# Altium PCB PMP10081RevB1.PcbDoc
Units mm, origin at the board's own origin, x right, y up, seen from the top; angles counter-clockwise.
Board outline 49.53 x 78.74 mm, 4 copper layers (Top Layer, inner 1, inner 2, Bottom Layer), stack 2.028 mm thick; 62 components, 28 nets, 143 pads, 49 vias.
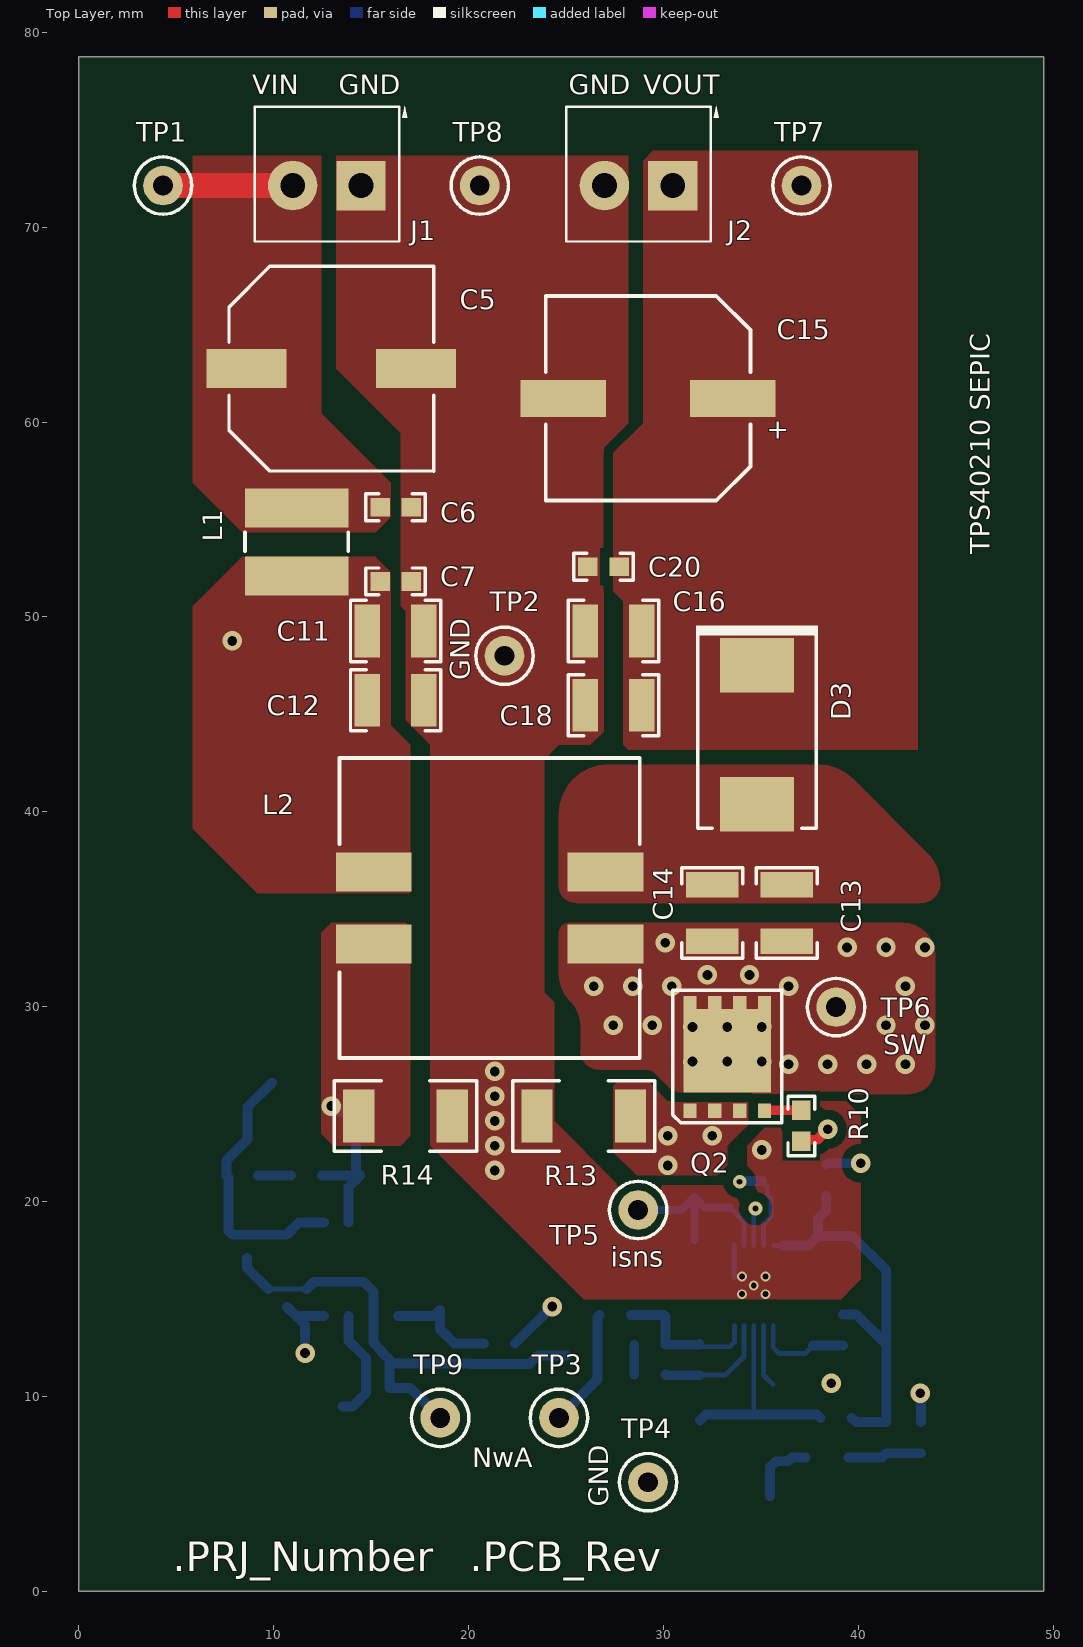
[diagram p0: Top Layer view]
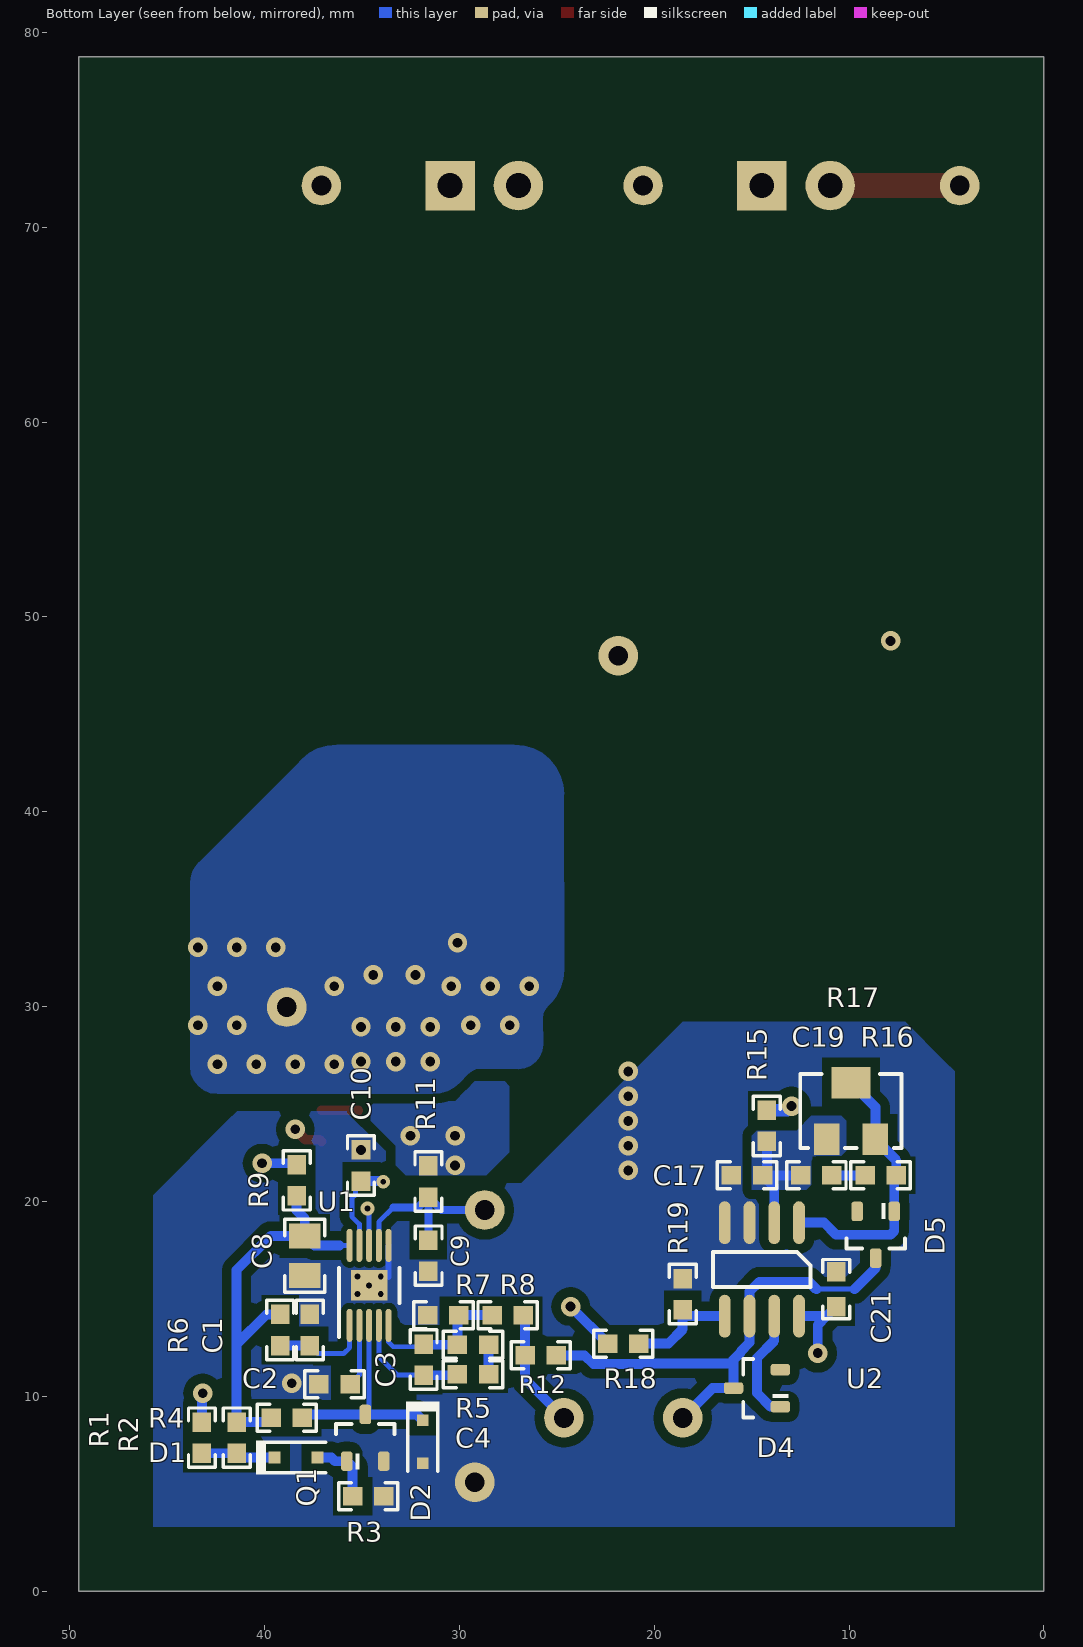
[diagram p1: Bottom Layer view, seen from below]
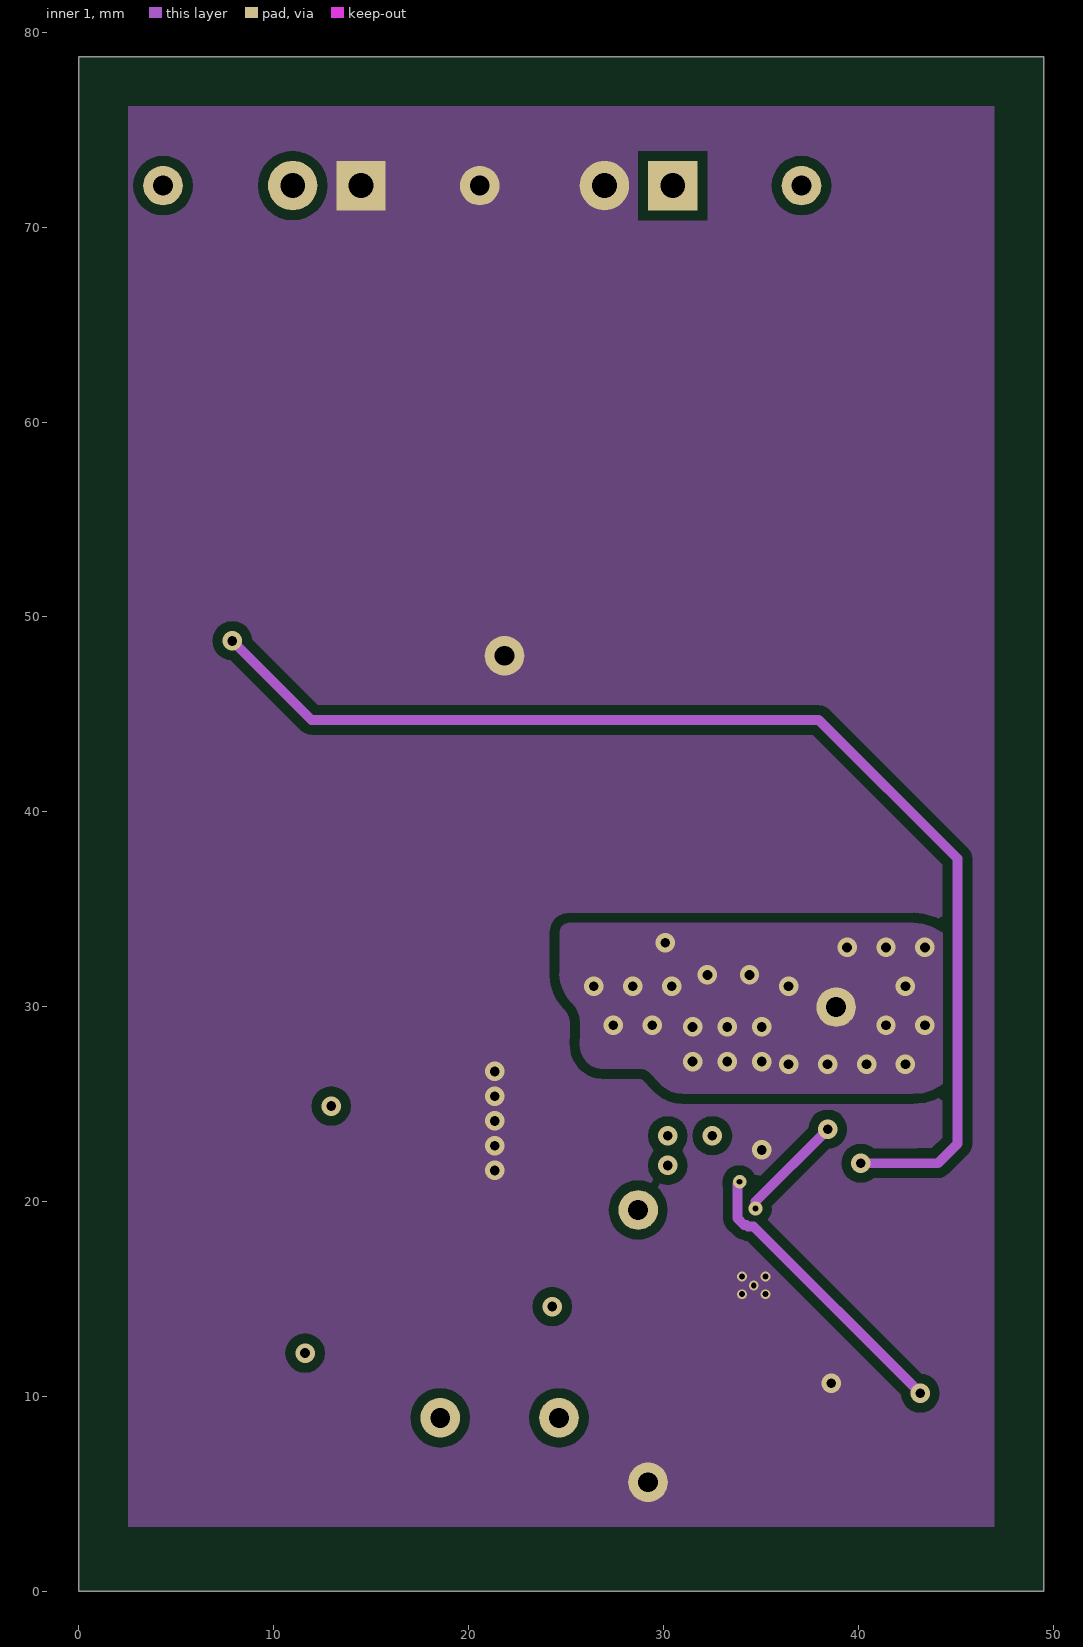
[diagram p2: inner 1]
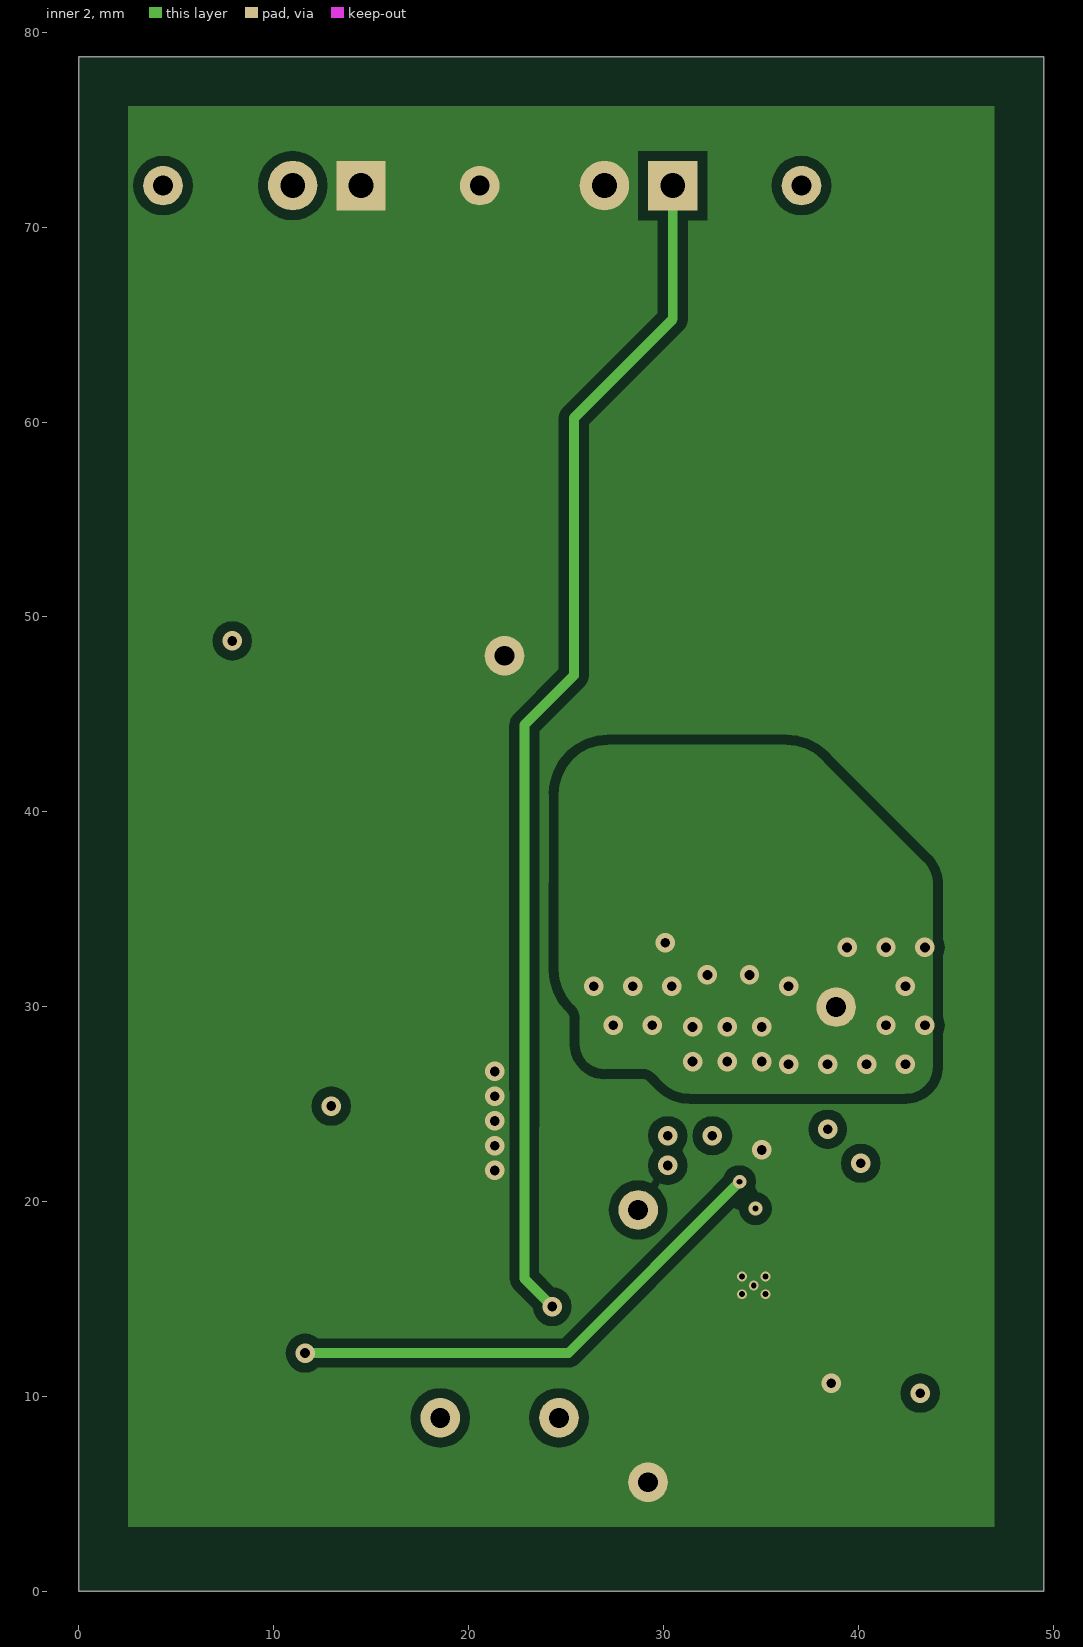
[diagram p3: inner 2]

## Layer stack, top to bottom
Top Solder: solder mask 0.0102, Solder Resist, Dk 3.5
Top Layer: signal copper 0.0356
Dielectric1: core 1.5037, FR-4, Dk 4.8
inner 1: signal copper 0.036
Dielectric 3: prepreg 0.127, Dk 4.2
inner 2: signal copper 0.036
Dielectric 2: core 0.254, Dk 4.2
Bottom Layer: signal copper 0.0356
Bottom Solder: solder mask 0.0102, Solder Resist, Dk 3.5

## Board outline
0,0 0,78.74 49.53,78.74 49.53,0

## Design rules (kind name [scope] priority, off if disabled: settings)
AcuteAngle [All] p1: minimum=4.50000000000000E+0001 checktracksonly=FALSE
AssemblyTestPointUsage [All] p1: valid=2
Clearance Clearance_Keepouts [((IsTrack Or IsArc) And Not InPoly) And IsFree and IsKeepOut vs ((IsTrack Or IsArc) And Not InPoly) And IsFree and IsKeepOut] p1: gap=0
Clearance Clearance_BoardEdge_MountingHoles [OnCopper and InComponentClass('Mounting Holes') vs IsKeepOut] p2: gap=1.016
Clearance Clearance_BoardEdge_Poly [OnCopper and InPoly vs IsKeepOut] p3: gap=0.635
Clearance Clearance_BoardEdge [OnCopper and Not InComponentClass('Logo') and not InComponentClass('FiducialMark') and not InRegion(1000,500,4000,800) and Not IsKeepout vs IsKeepOut] p4: gap=1.5
Clearance Clearance_U1 [InComponent('U1')] p5: gap=0.3
Clearance Clearance_Poly [InPolygon] p6: gap=0.5
Clearance [All] p7: gap=0.32
ComponentClearance ComponentClearance_MountingHoles_FiducialMarks [InComponentClass('Mounting Holes') vs InComponentClass('FiducialMark')] p1: gap=1.27 collisioncheckmode=3 verticalgap=0.254 showdistances=FALSE
ComponentClearance ComponentClearance_Shunt [InComponentClass('Header') vs InComponentClass('Shunt')] p2: gap=0 collisioncheckmode=3 verticalgap=0 showdistances=FALSE
ComponentClearance ComponentClearance_Logo [InComponentClass('Logo')] p3: gap=1.27 collisioncheckmode=3 verticalgap=0.254 showdistances=FALSE
ComponentClearance ComponentClearance_ScrewToNut [(HasFootprint('NY PMS 440 0025 PH')) vs (HasFootprint('Keystone_1902C'))] p4: gap=0.127 collisioncheckmode=3 verticalgap=0.254 showdistances=FALSE
ComponentClearance ComponentClearance_MountingHoles [InComponentClass('Mounting Holes')] p5: gap=6.35 collisioncheckmode=3 verticalgap=2540 showdistances=FALSE
ComponentClearance ComponentClearance_SmallPassives [HasFootprint('0201*') or HasFootprint('0402*') or HasFootprint('0508') or HasFootprint('0603*') or HasFootprint('0612') or HasFootprint('0805*') or HasFootprint('0815*') or HasFootprint('0830*') or HasFootprint('1206*') or HasFootprint('1210*') or HasFootprint('1808*') or HasFootprint('1812*') or HasFootprint('1825*') or HasFootprint('2010*') or HasFootprint('2220*') or HasFootprint('2225*') or HasFootprint('2512*') or HasFootprint('2728*') or HasFootprint('3518*') vs HasFootprint('0201*') or HasFootprint('0402*') or HasFootprint('0508') or HasFootprint('0603*') or HasFootprint('0612') or HasFootprint('0805*') or HasFootprint('0815*') or HasFootprint('0830*') or HasFootprint('1206*') or HasFootprint('1210*') or HasFootprint('1808*') or HasFootprint('1812*') or HasFootprint('1825*') or HasFootprint('2010*') or HasFootprint('2220*') or HasFootprint('2225*') or HasFootprint('2512*') or HasFootprint('2728*') or HasFootprint('3518*')] p6: gap=0.508 collisioncheckmode=3 verticalgap=0.254 showdistances=FALSE
ComponentClearance ComponentClearance_THtoSMT [IsThruComponent vs IsSMTComponent] p7: gap=1.27 collisioncheckmode=3 verticalgap=0.762 showdistances=FALSE
ComponentClearance ComponentClearance_THtoTH [IsThruComponent vs IsThruComponent] p8: gap=3 collisioncheckmode=3 verticalgap=0.762 showdistances=FALSE
ComponentClearance [All] p9: gap=0.8 collisioncheckmode=3 verticalgap=0.254 showdistances=FALSE
DiffPairsRouting [All] p1: maxlimit=2.54 minlimit=0.254 mostfreqgap=0.254 toplayer_minwidth=0.381 toplayer_maxwidth=0.381 toplayer_prefwidth=0.381 midlayer1_minwidth=0.381 midlayer1_maxwidth=0.381 midlayer1_prefwidth=0.381 midlayer2_minwidth=0.381 midlayer2_maxwidth=0.381 midlayer2_prefwidth=0.381 bottomlayer_minwidth=0.381 bottomlayer_maxwidth=0.381 bottomlayer_prefwidth=0.381 maxuncoupledlength=25.4
FabricationTestPointUsage TestPointUsage [All] p1: valid=2 allowmultiple=FALSE
FabricationTestpoint Testpoint [All] p1: side=3 testpointundercomponent=TRUE minsize=1.016 maxsize=2.54 preferedsize=1.524 minholesize=0 maxholesize=1.016 preferedholesize=0.813 testpointgrid=0.025 allowsidetop=TRUE allowsidebottom=TRUE usegrid=TRUE gridtolerance=0
FanoutControl Fanout_LCC [IsLCC] p1: bgadir=Out bgaviamode=Centered fanoutstyle=Auto fanoutdirection=Alternating viagrid=0.025 // Fanout_LCC (Default Rule)
FanoutControl Fanout_BGA [IsBGA] p2: bgadir=Out bgaviamode=Centered fanoutstyle=Auto fanoutdirection=Alternating viagrid=0.025 // Fanout_BGA (Default Rule)
FanoutControl Fanout_Default [All] p4: bgadir=Out bgaviamode=Centered fanoutstyle=Auto fanoutdirection=Alternating viagrid=0.025 // Fanout_Default (Default Rule)
FanoutControl Fanout_Small [(CompPinCount < 5)] p5: bgadir=Out bgaviamode=Centered fanoutstyle=Auto fanoutdirection=OutThenIn viagrid=0.025 // Fanout_Small (Default Rule)
HoleSize [All] p1: absolutevalues=TRUE maxlimit=7 minlimit=0.3 maxpercent=80.000 minpercent=20.000
MinimumAnnularRing MinimumAnnularRing_ThermalPadVias [IsVia and InAnyComponent] p1: minimumring=0.15
MinimumAnnularRing [All] p2: minimumring=0.2
MinimumSolderMaskSliver MinimumSolderMaskSliver_Logo [InComponentClass('Logo') vs InComponentClass('Logo')] p1: minsoldermaskwidth=0.018
MinimumSolderMaskSliver [All] p2: minsoldermaskwidth=0.1
PlaneConnect [All] p1: planeconnectstyle=Relief reliefexpansion=0.254 reliefentries=4 reliefconductorwidth=0.254 reliefairgap=0.254
PolygonConnect [All] p1: connectstyle=Direct reliefconductorwidth=0.254 reliefentries=4 polygonreliefangle="90 Angle" airgapwidth=0.254
RoutingVias ThermalPadVias [IsVia and InAnyComponent] p1: holewidth=0.3 width=0.7 viastyle="Through Hole" minholewidth=0.3 minwidth=0.5 maxholewidth=0.5 maxwidth=1
RoutingVias [All] p2: holewidth=0.5 width=0.7 viastyle="Through Hole" minholewidth=0.3 minwidth=0.7 maxholewidth=1.016 maxwidth=1.651
SilkToBoardRegionClearance [Not ((IsComment or IsDesignator) And (Hide <> 'False')) and not InRegion(1000,500,4000,800)] p1:
SilkToSilkClearance SilkToSilkClearance_Pb-FreeLogo [(HasFootprint('Pb-Free_Overlay_Medium') OR HasFootprint('Pb-Free_Overlay_Small')) vs (HasFootprint('Pb-Free_Overlay_Medium') OR HasFootprint('Pb-Free_Overlay_Small'))] p1: silktosilkclearance=0
SilkToSilkClearance [All] p2: silktosilkclearance=0.127
SilkToSolderMaskClearance "Silk to Solder Mask Opening" [All] p1: minsilkscreentomaskgap=0.025 clearancetoexposedcopper=FALSE
SolderMaskExpansion [All] p1: expansion=0.05
UnpouredPolygon [All] p1: allowunpoured=FALSE
Width [All] p1: maxlimit=2.54 minlimit=0.152 preferedwidth=0.254 checkconnectedcopper=TRUE
14 further rules are at their usual default settings.

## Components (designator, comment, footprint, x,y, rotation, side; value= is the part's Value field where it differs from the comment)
C1 "GRM188R71H331KA01D" 0603#1 37.684,13.404 r90 bottom
C2 "GRM188R71E224KA88D" 0603#1 36.414,10.61 r0 bottom
C3 "GRM1885C1H151JA01D" 0603#1 31.842,11.88 r90 bottom
C4 "GRM188R71H223KA01D" 0603#1 29.302,11.118 r180 bottom
C5 "EEE-FK1H221GP" SM_RADIAL_G 12.954,62.738 r0 top
C6 "GRM188R71H104KA93D" 0603#1 16.256,55.626 r0 top
C7 "GRM188R71H104KA93D" 0603#1 16.256,51.816 r0 top
C8 "GRM21BR71H105KA12L" 0805_HV 37.938,17.214 r270 bottom
C9 "06033C101KAT2A" 0603#1 31.588,17.214 r270 bottom
C10 "GRM188R71E105KA12D" 0603#1 35.052,21.844 r90 bottom
C11 "GRM32ER71H106KA12L" 1210 16.256,49.276 r0 top
C12 "GRM32ER71H106KA12L" 1210 16.256,45.72 r0 top
C13 "GRM32ER71H106KA12L" 1210 36.322,34.798 r90 top
C14 "GRM32ER71H106KA12L" 1210 32.512,34.798 r90 top
C15 "25SVPF330M" CAPSMT_62_F12 29.21,61.214 r180 top
C16 "GRM32ER71E226KE15L" 1210 27.432,49.276 r180 top
C17 "GRM188R71H102KA01D" 0603#1 15.24,21.336 r180 bottom
C18 "GRM32ER71E226KE15L" 1210 27.432,45.466 r180 top
C19 "GRM188R71H103KA01D" 0603#1 11.684,21.336 r0 bottom
C20 "GRM188R71H104KA93D" 0603#1 26.924,52.578 r180 top
C21 "GCM188R71H104KA57D" 0603#2 10.668,15.494 r270 bottom
D1 "MMSZ5235BS-7-F" sod-323 38.387,6.858 r180 bottom
D2 "MMSZ5235BS-7-F" sod-323 31.885,7.663 r270 bottom
D3 "B560C-13-F" SMC 34.798,43.942 r270 top
D4 "BAS16-7-F" SOT-23 14.732,10.414 r0 bottom
D5 "BAS16-7-F" SOT-23 8.636,18.288 r270 bottom
J1 "ED555/2DS" TERM_BLK_ED555-2DS 14.478,72.136 r180 top
J2 "ED555/2DS" TERM_BLK_ED555-2DS 30.48,72.136 r180 top
L1 "74408943022" WE-SPC_4838 11.176,53.848 r270 top
L2 "MSD1583-223MEB" IND_MSD1583 21.082,35.052 r0 top
Q1 "MMBT2222A" SOT-23 34.831,7.866 r90 bottom
Q2 "CSD18563Q5A" TRANS_NexFET_Q5A 33.274,27.432 r90 top
R1 "CRCW0603100KFKEA" 0603#1 43.213,7.874 r90 bottom
R2 "CRCW060320K0FKEA" 0603#1 41.435,7.874 r90 bottom
R3 "CRCW0603100KFKEA" 0603#1 34.679,4.869 r0 bottom
R4 "CRCW060320K0FKEA" 0603#1 38.862,8.89 r0 bottom
R5 "CRCW0603100KFKEA" 0603#1 29.302,12.642 r180 bottom
R6 "CRCW0603182KFKEA" 0603#1 39.208,13.404 r90 bottom
R7 "CRCW06033K92FKEA" 0603#1 30.826,14.166 r180 bottom
R8 "CRCW060310K0FKEA" 0603#1 27.524,14.166 r180 bottom
R9 "CRCW06034R64FKEA" 0603#1 38.354,21.082 r90 bottom
R10 "CRCW06034R64FKEA" 0603#1 37.084,23.876 r270 top
R11 "CRCW06031K00FKEA" 0603#1 31.588,21.024 r90 bottom
R12 "CRCW060349R9FKEA" 0603#1 25.826,12.099 r180 bottom
R13 "CSRN2010FK25L0" 2010M 25.908,24.384 r0 top
R14 "CSRN2010FK25L0" 2010M 16.764,24.384 r0 top
R15 "CRCW060310K0FKEA" 0603#1 14.224,23.876 r270 bottom
R16 "CRCW060346K4FKEA" 0603#1 8.382,21.336 r180 bottom
R17 "3224W-1-205E" TRIM_3224W 9.906,24.638 r90 bottom
R18 "CRCW060390K9FKEA" 0603#1 21.59,12.7 r0 bottom
R19 "CRCW060320K0FKEA" 0603#1 18.542,15.24 r270 bottom
TP1 "5000" Keystone5000 4.318,72.136 r0 top
TP2 "5001" Keystone5001 21.844,48.006 r0 top
TP3 "5003" Keystone5003 24.638,8.89 r0 top
TP4 "5001" Keystone5001 29.21,5.588 r0 top
TP5 "5002" Keystone5002 28.702,19.558 r0 top
TP6 "5002" Keystone5002 38.862,29.972 r0 top
TP7 "5000" Keystone5000 37.084,72.136 r0 top
TP8 "5001" Keystone5001 20.574,72.136 r0 top
TP9 "5000" Keystone5000 18.542,8.89 r0 top
U1 "TPS40210DGQR" DGQ0010D_N 34.636,15.69 r90 bottom
U2 "TLC272CD" D0008A_N 14.478,16.51 r270 bottom

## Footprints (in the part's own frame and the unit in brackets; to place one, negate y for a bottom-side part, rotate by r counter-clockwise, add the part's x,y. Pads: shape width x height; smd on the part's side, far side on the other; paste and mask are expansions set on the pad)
0603#1 [mm] "0603 from SM-752 data"
  rect 1x0.95 smd: 1(-0.8,0) 2(0.8,0)
  silkscreen extent -1.52,-0.69 1.52,0.69, body extent -0.87,-0.47 0.87,0.47, height 0.85
0603#2 [mm] "0603 from SM-752 data"
  rect 1x0.95 smd: 1(-0.9,0) 2(0.9,0)
  silkscreen extent -1.52,-0.69 1.52,0.69, body extent -0.87,-0.47 0.87,0.47, height 0.85
0805_HV [mil] "0805 with 30mil clearance between pads"
  rect 50x63 smd: 1(-40,0) 2(40,0)
  silkscreen extent -74,-40 74,40, body extent -43,-29 43,29, height 43
1210 [mm] "1210 from SM-752 data"
  rect 1.3x2.7 smd: 1(-1.45,0) 2(1.45,0)
  silkscreen extent -2.32,-1.57 2.32,1.57, body extent -1.7,-1.35 1.7,1.35, height 1.35
2010M [mm]
  rect 1.6x2.7 smd: 1(-2.4,0) 2(2.4,0)
  silkscreen extent -3.65,-1.8 3.65,1.8, body extent -2.73,-1.45 2.73,1.45, height 1.66
CAPSMT_62_F12 [mm] "F12, SMD, 2-Leads, Body 10.5x10.5mm, Height 12.7mm"
  rect 4.4x1.9 smd: 1(-4.35,0) 2(4.35,0)
  silkscreen extent -5.25,-5.25 5.25,5.25, body extent -5.25,-5.25 5.25,5.25, height 12.71
D0008A_N [mm] "SOIC, 8-Leads, Body 4.9x3.9mm, Pitch 1.27mm, IPC Medium Density"
  oval 2.2x0.6 smd: 1(-2.4,1.905) 2(-2.4,0.635) 3(-2.4,-0.635) 4(-2.4,-1.905) 5(2.4,-1.905) 6(2.4,-0.635) 7(2.4,0.635) 8(2.4,1.905)
  silkscreen extent -0.9,-2.5 0.9,2.5, body extent -3,-2.45 3,2.45, height 1.63
DGQ0010D_N [mm] "TSSOP, 10-Leads, Body 3x3mm, Pitch 0.5mm, Thermal Pad 1.88x1.57mm, IPC Medium Density"
  oval 1.7x0.3 smd: 1(-2.05,1) 2(-2.05,0.5) 3(-2.05,0) 4(-2.05,-0.5) 5(-2.05,-1) 6(2.05,-1) 7(2.05,-0.5) 8(2.05,0) 9(2.05,0.5) 10(2.05,1)
  rect 1.57x1.88 smd: 11(0,0)
  silkscreen extent -2.65,-1.55 0.9,1.55, body extent -2.45,-1.5 2.45,1.5, height 0.94
IND_MSD1583 [mm] "COILCRAFT"
  rect 3.9x2 smd: 1(-5.95,1.85) 2(-5.95,-1.85) 3(5.95,-1.85) 4(5.95,1.85)
  silkscreen extent -7.7,-7.7 7.7,7.7, body extent -7.55,-7.55 7.55,7.55, height 8.6
Keystone5000 [mil] "For Keystone 500x miniature loop terminals"
  round 80 hole 40: 1(0,0)
  silkscreen extent -58,-58 58,58, body extent -49,-49 49,49, height 182
Keystone5001 [mil] "For Keystone 500x miniature loop terminals"
  round 80 hole 40: 1(0,0)
  silkscreen extent -58,-58 58,58, body extent -49,-49 49,49, height 182
Keystone5002 [mil] "For Keystone 500x miniature loop terminals"
  round 80 hole 40: 1(0,0)
  silkscreen extent -58,-58 58,58, body extent -49,-49 49,49, height 182
Keystone5003 [mil] "For Keystone 500x miniature loop terminals"
  round 80 hole 40: 1(0,0)
  silkscreen extent -58,-58 58,58, body extent -49,-49 49,49, height 182
SM_RADIAL_G [mm] "10 x 10.2mm:  Panasonic G"
  rect 4.1x2 smd: 1(-4.35,0) 2(4.35,0)
  silkscreen extent -5.25,-5.25 5.25,5.25, body extent -5.26,-5.26 5.26,5.26, height 10.5
SMC [mil] "Molded Diode, 2-Leads, Body 6.9x5.8mm, IPC Medium Density, based on OnSemi component dimensions and land patterns"
  rect 110x150 smd: 1(-140.49,0) 2(140.49,0)
  silkscreen extent -221,-124 189,123, body extent -156,-116 156,116, height 91
sod-323 [mm] "NXP recommended land pattern"
  rect 0.6x0.6 smd paste-0.05: 1(-1.1,0) 2(1.1,0)
  silkscreen extent -2.06,-0.86 1.53,0.86, body extent -1.3,-0.67 1.3,0.68, height 1.1
SOT-23 [mm] "SOT23, 3-Leads, Body 2.9x1.3mm, Pitch 0.95mm, Lead Span 2.5mm, IPC Medium Density"
  rrect50% 1x0.6 smd: 1(-1.2,0.95) 2(-1.2,-0.95) 3(1.2,0)
  silkscreen extent -1.63,-1.5 0.7,1.5, body extent -1.16,-1.45 1.21,1.45, height 1
TERM_BLK_ED555-2DS [mil]
  rect 100x100 hole 50: 1(0,0)
  round 100 hole 50: 2(138,0)
  silkscreen extent -93,-161 215,113, body extent -69,-150 207,106, height 323
TRANS_NexFET_Q5A [mm] "TI recommended land pattern (nominal) M0139-01"
  rect 0.75x0.675 smd paste-0.1 mask+0.051: 1(-2.776,1.917) 2(-2.776,0.639) 3(-2.776,-0.639) 4(-2.776,-1.917)
  rect 0.655x0.675 smd paste-0.1 mask+0.051: 5(2.776,-1.917) 6(2.776,-0.639) 7(2.776,0.639) 8(2.776,1.917)
  rect 4.295x4.51 smd paste-2.2 mask+0.051: 9(0.301,0)
  silkscreen extent -3.4,-2.8 3.4,2.8, body extent -3.05,-2.5 3.05,2.5, height 1.11
TRIM_3224W [mm] "BOURNS"
  rect 1.6x1.3 smd: 1(-1.45,1.25) 3(-1.45,-1.25)
  rect 1.6x2 smd: 2(1.45,0)
  silkscreen extent -1.9,-2.6 1.9,2.6, body extent -1.8,-2.5 1.8,2.5, height 5.31
WE-SPC_4838 [mm] "WURTH"
  rect 2x5.3 smd: 1(-1.75,0) 2(1.75,0)
  silkscreen extent -0.48,-2.65 0.48,2.65, body extent -2.55,-2.55 2.55,2.55, height 4.1

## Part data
C1: "CAP, CERM, 330pF, 50V, +/-10%, X7R, 0603"
C2: "CAP, CERM, 0.22uF, 25V, +/-10%, X7R, 0603"
C3: "CAP, CERM, 150pF, 50V, +/-5%, C0G/NP0, 0603"
C4: "CAP, CERM, 0.022uF, 50V, +/-10%, X7R, 0603"
C5: "CAP, AL, 220uF, 50V, +/-20%, 0.18 ohm, SMD"
C6 C7 C20: "CAP, CERM, 0.1 µF, 50 V, +/- 10%, X7R, 0603"
C8: "CAP, CERM, 1uF, 50V, +/-10%, X7R, 0805"
C9: "CAP, CERM, 100pF, 25V, +/-10%, X7R, 0603"
C10: "CAP, CERM, 1uF, 25V, +/-10%, X7R, 0603"
C11 C12 C13 C14: "CAP, CERM, 10uF, 50V, +/-10%, X7R, 1210"
C15: "CAP, Polymer, 330 µF, 25 V, +/- 20%, 0.014 ohm, F12, SMD, 2-Leads, Body 10.5x10.5mm, Height 12.7mm SMD"
C16 C18: "CAP, CERM, 22uF, 25V, +/-10%, X7R, 1210"
C17: "CAP, CERM, 1000pF, 50V, +/-10%, X7R, 0603"
C19: "CAP, CERM, 0.01uF, 50V, +/-10%, X7R, 0603"
C21: "CAP, CERM, 0.1uF, 50V, +/-10%, X7R, 0603"
D1 D2: "Diode, Zener, 6.8V, 200mW, SOD-323"
D3: "Diode, Schottky, 60V, 5A, SMC"
D4 D5: "Diode, Ultrafast, 75V, 0.3A, SOT-23"
J1 J2: "Terminal Block, 6A, 3.5mm Pitch, 2-Pos, TH"
L1: "Inductor, Shielded Drum Core, Ferrite, 2.2 µH, 3 A, 0.026 ohm, SMD"
L2: library part MSD1583-473MEB, "Coupled inductor, 22uH, 2.44A, 0.033 ohm, +/-20%, SMD"
Q1: library part "MMBT2222A, Fairchild Semiconductor", "Transistor, NPN, 40V, 0.15A, SOT-23"
Q2: "MOSFET, N-CH, 60V, 15A, SON 5x6mm"
R1 R3 R5: "RES, 100k ohm, 1%, 0.1W, 0603"
R2 R4 R19: "RES, 20.0k ohm, 1%, 0.1W, 0603"
R6: "RES, 182k ohm, 1%, 0.1W, 0603"
R7: "RES, 3.92k ohm, 1%, 0.1W, 0603"
R8 R15: "RES, 10.0k ohm, 1%, 0.1W, 0603"
R9 R10: "RES, 4.64 ohm, 1%, 0.1W, 0603"
R11: "RES, 1.00k ohm, 1%, 0.1W, 0603"
R12: "RES, 49.9 ohm, 1%, 0.1W, 0603"
R13 R14: "RES, 0.025 ohm, 1%, 1W, 2010"
R16: "RES, 46.4k ohm, 1%, 0.1W, 0603"
R17: "TRIMMER 2M OHM 0.25W SMD"
R18: "RES, 90.9k ohm, 1%, 0.1W, 0603"
TP1 TP7 TP9: "Test Point, Miniature, Red, TH"
TP2 TP4 TP8: "Test Point, Miniature, Black, TH"
TP3: "Test Point, Miniature, Orange, TH"
TP5 TP6: "Test Point, Miniature, White, TH"
U1: "4.5-V TO 52-V INPUT CURRENT MODE BOOST CONTROLLER, DGQ0010D"
U2: "IC, Precision Dual Operational Amplifiers"

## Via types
v1: diameter 1, hole 0.5, Top Layer to Bottom Layer, tented both sides, 17 vias
v2: diameter 1, hole 0.5, Top Layer to Bottom Layer, tented top, 16 vias
v3: diameter 1, hole 0.5, Top Layer to Bottom Layer, tented bottom, 6 vias
v4: diameter 0.5, hole 0.3, Top Layer to Bottom Layer, 5 vias
v5: diameter 1, hole 0.5, Top Layer to Bottom Layer, 3 vias
v6: diameter 0.7, hole 0.3, Top Layer to Bottom Layer, tented both sides, 2 vias

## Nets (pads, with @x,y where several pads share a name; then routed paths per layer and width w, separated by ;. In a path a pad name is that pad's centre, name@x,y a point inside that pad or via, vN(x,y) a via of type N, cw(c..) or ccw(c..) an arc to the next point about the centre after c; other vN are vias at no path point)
8VBIAS: C10.1 C21.2 R1.2 U1.9 U2.8 | length 51.5
  inner 1 w0.508: v6(33.909,21.006) 33.798,20.895 33.798,19.134 34.136,18.796 34.253,18.796 34.339,18.71 34.63,18.71 v1(43.18,10.16)
  inner 2 w0.508: v1(11.608,12.217) 25.121,12.217 v6(33.909,21.006)
  Bottom Layer w0.254: C10.1 35.328,20.768 35.328,20.346 35.519,20.155 35.519,19.219 35.136,18.836 U1.9
  Bottom Layer w0.508: C21.2 11.152,14.11 ; v1(11.608,12.217) 11.608,13.654 11.152,14.11 ; U2.8 11.152,14.11 ; v6(33.909,21.006) 33.947,21.044 C10.1 ; v1(43.18,10.16) 43.213,10.127 R1.2
CS: D4.3 D5.3 R12.2 TP9.1 U2.6 | length 25.7
  Bottom Layer w0.254: 9.728,15.494 11.684,15.494
  Bottom Layer w0.508: D5.3 8.636,16.586 9.728,15.494 ; 11.684,15.494 12.065,15.875 14.605,15.875 15.113,15.367 U2.6 15.113,12.752 15.56,12.305 15.56,12.246 15.932,11.874 ; TP9.1 17.018,10.414 D4.3 15.932,11.874 ; R12.2 23.576,12.099 23.128,11.651 20.052,11.651 20.019,11.684 16.122,11.684 15.932,11.874
GND: C1.2 C2.2 C5.2 C6.2 C7.2 C8.2 C9.2 C10.2 C11.2 C12.2 C15.2 C16.2 C17.1 C18.2 C20.2 C21.1 D2.2 J1.1 J2.2 Q1.2 R3.1 R7.1 R13.1 R14.2 R19.1 TP2.1 TP4.1 TP8.1 U1.6 U1.11 U2.3 U2.4 | length 1.6
  Bottom Layer w0.305: 33.636,16.11 U1.6
  other v1: 38.608,10.668 35.052,22.644 21.336,22.86 21.336,25.4
  other v4: 34.036,15.24 35.236,15.24 34.636,15.69 34.036,16.14 35.236,16.14
  other v5: 21.336,21.59 21.336,24.13 21.336,26.67
NetC1_1: C1.1 R6.1 U1.1 | length 5
  Bottom Layer w0.254: U1.1 35.636,12.497 35.941,12.192 37.272,12.192 C1.1
  Bottom Layer w0.508: C1.1 R6.1
NetC2_1: C2.1 U1.2 | length 3.2
  Bottom Layer w0.254: U1.2 35.136,11.088 C2.1
NetC3_1: C3.1 C4.1 U1.4 | length 6
  Bottom Layer w0.254: C3.1 33.178,11.08 34.136,12.038 U1.4
  Bottom Layer w0.508: C4.1 30.14,11.08 C3.1
NetC3_2: C3.2 R5.1 R7.2 R8.1 U1.5 | length 7.8
  Bottom Layer w0.254: C3.2 31.982,12.54 33.401,12.54 33.636,12.775 U1.5
  Bottom Layer w0.508: R8.1 R7.2 30.102,14.09 R5.1 31.804,12.642 C3.2
NetC4_2: C4.2 R5.2 | length 1.5
  Bottom Layer w0.508: C4.2 R5.2
NetC5_1: C5.1 C6.1 J1.2 L1.1 TP1.1 | length 6.7
  Top Layer w1.27: TP1.1 J1.2
NetC7_1: C7.1 C11.1 C12.1 L1.2 L2.1 R9.2 | length 63.7
  inner 1 w0.508: v1(7.874,48.768) 11.938,44.704 37.973,44.704 45.085,37.592 45.085,22.958 44.084,21.956 v1(40.132,21.956)
  Bottom Layer w0.508: R9.2 38.428,21.956 v1(40.132,21.956)
NetC8_1: C8.1 R2.2 R4.2 R6.2 R9.1 U1.10 | length 21.5
  Bottom Layer w0.254: U1.10 36.155,17.74
  Bottom Layer w0.508: 36.155,17.74 37.448,17.74 C8.1 ; R9.1 38.354,19.532 37.938,19.116 C8.1 ; R6.2 39.898,14.204 41.435,12.667 ; R4.2 39.878,8.674 R2.2 41.435,12.667 ; C8.1 39.682,18.23 41.435,16.477 41.435,12.667
NetC9_1: C9.1 R11.1 TP5.1 U1.7 | length 9.7
  Bottom Layer w0.254: 33.401,19.685 34.136,18.95 U1.7
  Bottom Layer w0.4: TP5.1 30.922,19.558 R11.1 ; C9.1 R11.1 ; 33.401,19.685 32.127,19.685 R11.1
NetC13_1: C13.1 C14.1 L2.3 Q2.5 Q2.6 Q2.7 Q2.8 Q2.9 TP6.1
  other v1: 32.258,31.623 34.417,31.623 30.099,33.274
  other v2: 36.423,27.036 38.423,27.036 40.423,27.036 42.423,27.036 27.423,29.036 29.423,29.036 41.423,29.036 43.423,29.036 26.423,31.036 28.423,31.036 30.423,31.036 36.423,31.036 42.423,31.036 39.423,33.036 41.423,33.036 43.423,33.036
  other v3: 31.496,27.178 33.274,27.178 35.052,27.178 31.496,28.956 33.274,28.956 35.052,28.956
NetC13_2: C13.2 C14.2 D3.2 L2.4
NetC15_1: C15.1 C16.1 C18.1 C20.1 D3.1 J2.1 R18.2 TP7.1 | length 64
  inner 2 w0.508: v1(24.295,14.605) 22.86,16.04 22.86,44.45 25.4,46.99 25.4,60.198 30.48,65.278 J2.1
  Bottom Layer w0.508: R18.2 v1(24.295,14.605)
NetC17_2: C17.2 C19.2 R15.2 R17.1 U2.2 | length 6.5
  Bottom Layer w0.508: C19.2 C17.2 ; U2.2 13.843,20.739 C17.2 ; R15.2 14.224,21.552 C17.2
NetC19_1: C19.1 R16.1 | length 1.7
  Bottom Layer w0.508: R16.1 C19.1
NetD1_1: D1.1 R1.1 R2.1 | length 3.8
  Bottom Layer w0.508: D1.1 41.219,6.858 R2.1 R1.1
NetD1_2: D1.2 Q1.1 R3.2 | length 3.5
  Bottom Layer w0.508: R3.2 35.479,6.364 Q1.1 36.384,6.666 36.576,6.858 D1.2
NetD2_1: D2.1 Q1.3 R4.1 U1.3 | length 11
  Bottom Layer w0.254: U1.3 34.636,9.261 Q1.3
  Bottom Layer w0.508: D2.1 32.188,9.066 Q1.3 37.886,9.066 R4.1
NetD4_1: D4.1 U2.7 | length 5.8
  Bottom Layer w0.508: D4.1 14.036,9.464 14.732,10.16 14.732,11.962 13.843,12.851 U2.7
NetD5_1: D5.1 R16.2 R17.2 R17.3 U2.1 | length 13.8
  Bottom Layer w0.508: R17.2 8.656,24.838 R17.3 7.582,22.114 R16.2 7.686,21.232 D5.1 7.686,18.476 7.874,18.288 10.668,18.288 11.29,18.91 U2.1
NetL2_2: L2.2 R14.1 R15.1 | length 1.4
  Bottom Layer w0.635: v1(12.954,24.892) 13.17,24.676 R15.1
NetQ2_1: Q2.1 Q2.2 Q2.3 R11.2 R13.2
  other v1: 30.226,21.844 30.226,23.368 32.512,23.368
NetQ2_4: Q2.4 R10.1 | length 1.9
  Top Layer w0.508: Q2.4 35.212,24.676 R10.1
NetR8_2: R8.2 R12.1 TP3.1 | length 6.1
  Bottom Layer w0.508: TP3.1 26.626,10.878 R12.1 26.626,14.068 R8.2
NetR10_2: R10.2 U1.8 | length 9.1
  Top Layer w0.508: R10.2 37.173,23.165 37.897,23.165 v1(38.43,23.698)
  inner 1 w0.508: v6(34.722,19.634) 34.722,19.99 v1(38.43,23.698)
  Bottom Layer w0.254: U1.8 34.636,19.548 v6(34.722,19.634)
NetR18_1: R18.1 R19.2 U2.5 | length 5.9
  Bottom Layer w0.508: U2.5 18.212,14.11 R19.2 18.542,13.437 19.279,12.7 R18.1
pads on no net: D4.2 D5.2

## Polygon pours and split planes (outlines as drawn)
NetC13_1 on Top Layer "Top Layer-No Net 2" (solid, remove dead copper, pour order 25): 25.146,34.299 42.282,34.299 cw(c42.282,32.639) 43.942,32.639 43.942,26.845 cw(c42.608,26.845) 42.608,25.512 31.351,25.512 31.093,25.512 cw(c31.093,26.652) 30.287,25.846 29.585,26.547 ccw(c29.068,26.03) 29.068,26.761 26.718,26.761 cw(c26.718,27.735) 25.744,27.735 25.744,28.999 ccw(c23.937,28.999) 25.215,30.277 cw(c26.607,31.669) 24.638,31.669 24.638,32.385 24.638,33.791 cw(c25.146,33.791) 25.146,34.299
NetC13_2 on Top Layer "Top Layer-No Net 1" (solid, remove dead copper, pour order 22): 25.4,35.306 43.18,35.306 ccw(c43.18,36.322) 44.196,36.322 ccw(c42.05,36.322) 43.567,37.84 43.434,37.973 39.733,41.674 ccw(c37.937,39.878) 37.937,42.418 37.719,42.418 27.178,42.418 ccw(c27.178,39.878) 24.638,39.878 24.638,39.751 24.638,36.195 ccw(c25.527,36.195) 25.527,35.306
NetC5_1 on Top Layer "Top Layer-vin" (solid, remove dead copper, pour order 47): 12.446,73.66 12.446,60.452 13.462,59.436 16.002,56.896 16.002,55.151 16.002,55.118 15.24,54.356 8.382,54.356 5.842,56.896 5.842,64.77 5.842,73.66
NetC7_1 on Top Layer "Top Layer-vin2" (solid, remove dead copper, pour order 48): 16.002,52.291 15.24,53.053 15.24,53.086 8.382,53.086 5.842,50.546 5.842,48.26 5.842,39.116 9.144,35.814 17.018,35.814 17.018,43.434 16.002,44.45
NetQ2_1 on Top Layer "Top Layer-No Net" (solid, remove dead copper, pour order 53): 30.48,25.146 34.29,25.146 34.544,24.892 34.544,24.13 33.274,22.86 33.274,22.098 33.274,21.844 32.766,21.336 28.63,21.336 27.432,22.534 27.432,25.834 27.432,25.908 27.686,26.162 29.21,26.162 29.718,25.654 30.226,25.146
NetC15_1 on Top Layer "Top Layer-vout" (solid, remove dead copper, pour order 54): 27.94,43.434 27.94,50.8 27.432,51.308 27.432,55.964 27.432,58.42 28.702,59.69 28.956,59.944 28.956,70.612 28.956,73.406 29.464,73.914 36.068,73.914 43.053,73.914 43.053,66.929 43.053,50.927 43.053,43.18 35.306,43.18 28.194,43.18
GND on Top Layer "Top Layer-pwrgnd" (solid, remove dead copper, pour order 55): 13.208,73.66 13.208,62.738 16.51,59.436 16.51,50.546 16.764,50.292 16.764,44.704 18.034,43.434 18.034,32.258 18.034,22.86 18.796,22.098 25.908,14.986 35.814,14.986 38.608,14.986 39.116,14.986 39.878,15.748 40.132,16.002 40.132,24.384 39.37,25.146 36.359,25.146 36.359,24.929 34.29,22.86 34.29,21.844 33.274,20.828 27.686,20.828 24.384,24.13 24.384,27.178 24.384,30.226 23.876,30.734 23.876,42.672 24.638,43.434 25.4,43.434 26.242,43.434 26.924,44.116 26.924,53.34 26.924,58.674 28.194,59.944 28.194,73.66
NetL2_2 on Top Layer "Top Layer-No Net" (solid, remove dead copper, pour order 56): 17.018,23.368 16.51,22.86 13.064,22.86 12.446,23.478 12.446,27.432 12.446,33.782 12.954,34.29 16.764,34.29 17.018,34.036 17.018,26.924
NetC13_1 on Bottom Layer "Bottom Layer-No Net 1" (solid, remove dead copper, pour order 20): 30.774,25.527 42.418,25.527 ccw(c42.418,26.924) 43.815,26.924 43.815,36.322 ccw(c42.282,36.322) 43.366,37.406 38.354,42.418 38.082,42.69 ccw(c36.286,40.894) 36.286,43.434 35.306,43.434 27.178,43.434 ccw(c27.178,40.894) 24.638,40.894 24.638,31.889 ccw(c27.178,31.889) 25.382,30.093 25.438,30.036 cw(c24.779,29.377) 25.711,29.377 25.711,28.067 ccw(c26.981,28.067) 26.981,26.797 28.448,26.797 28.908,26.797 cw(c28.908,25.86) 29.57,26.522 29.998,26.095 ccw(c31.369,27.466) 31.369,25.527
NetQ2_1 on Bottom Layer "Top Layer-No Net" (solid, remove dead copper, pour order 52): 30.48,25.146 34.29,25.146 34.544,24.892 34.544,24.13 33.274,22.86 33.274,22.098 33.274,21.844 32.766,21.336 28.63,21.336 27.432,22.534 27.432,25.834 27.432,25.908 27.686,26.162 29.21,26.162 29.718,25.654 30.226,25.146
NetC17_2 on Bottom Layer "Top Layer-No Net" (solid, remove dead copper, pour order 57): 14.986,20.611 12.188,20.611 11.938,20.861 11.938,22.098 11.684,22.352 10.414,22.352 10.16,22.606 10.16,24.13 10.414,24.384 11.938,24.384 12.7,23.622 14.224,23.622 14.732,23.622 14.986,23.368
GND on Bottom Layer "bottom Layer-No Net" (solid, remove dead copper, pour order 65): 45.72,3.302 45.72,20.32 41.91,24.13 41.402,24.638 35.774,24.638 35.774,24.561 34.327,23.114 33.819,22.606 33.782,22.606 33.782,21.479 33.083,20.78 32.932,20.93 26.822,20.93 18.542,29.21 7.112,29.21 5.08,27.178 4.572,26.67 4.572,3.302
NetC13_1 on inner 2 "Bottom Layer-No Net 1" (solid, remove dead copper, pour order 20): 30.774,25.527 42.418,25.527 ccw(c42.418,26.924) 43.815,26.924 43.815,36.322 ccw(c42.282,36.322) 43.366,37.406 38.354,42.418 38.082,42.69 ccw(c36.286,40.894) 36.286,43.434 35.306,43.434 27.178,43.434 ccw(c27.178,40.894) 24.638,40.894 24.638,31.889 ccw(c27.178,31.889) 25.382,30.093 25.438,30.036 cw(c24.779,29.377) 25.711,29.377 25.711,28.067 ccw(c26.981,28.067) 26.981,26.797 28.448,26.797 28.908,26.797 cw(c28.908,25.86) 29.57,26.522 29.998,26.095 ccw(c31.369,27.466) 31.369,25.527
GND on inner 2 "L3-No Net" (solid, remove dead copper, pour order 60): 46.99,3.302 46.99,76.2 2.54,76.2 2.54,3.302
GND on inner 2 "bottom Layer-No Net" (solid, remove dead copper, pour order 63): 45.72,3.302 45.72,20.32 41.91,24.13 41.402,24.638 35.774,24.638 35.774,24.561 34.327,23.114 33.819,22.606 33.782,22.606 33.782,21.479 33.083,20.78 32.932,20.93 26.822,20.93 18.542,29.21 7.112,29.21 5.08,27.178 4.572,26.67 4.572,3.302
GND on inner 1 "L3-No Net" (solid, remove dead copper, pour order 62): 46.99,3.302 46.99,76.2 2.54,76.2 2.54,3.302
GND on inner 1 "bottom Layer-No Net" (solid, remove dead copper, pour order 58): 45.72,3.302 45.72,20.32 41.91,24.13 41.402,24.638 35.774,24.638 35.774,24.561 34.327,23.114 33.819,22.606 33.782,22.606 33.782,21.479 33.083,20.78 32.932,20.93 26.822,20.93 18.542,29.21 7.112,29.21 5.08,27.178 4.572,26.67 4.572,3.302
NetC13_1 on inner 1 "L2-sw" (solid, remove dead copper, pour order 61): 30.988,25.527 42.799,25.527 ccw(c42.799,28.067) 45.339,28.067 45.339,29.337 45.339,31.75 ccw(c42.799,31.75) 42.799,34.29 25.146,34.29 ccw(c25.146,33.819) 24.675,33.819 24.675,31.796 24.675,31.67 ccw(c26.717,31.67) 25.273,30.226 cw(c24.192,29.145) 25.721,29.145 25.721,28.695 25.721,28 ccw(c26.924,28) 26.924,26.797 28.829,26.797 cw(c28.829,26.184) 29.263,26.617 29.845,26.035 29.904,25.976 ccw(c30.988,27.06) 30.988,25.527

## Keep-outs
Keep-Out Layer:
  text ".Layer_Name" at 14.656,-21.806 h1.52

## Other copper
Top Layer:
  text ".Layer_Name" at 14.656,-21.806 h1.52
Bottom Layer:
  text ".Layer_Name" at 14.656,-21.806 h1.52

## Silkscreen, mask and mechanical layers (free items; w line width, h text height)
Top Overlay:
  text "VIN" at 8.89,76.835 h1.02
  text "GND" at 13.335,76.835 h1.02
  text "GND" at 25.146,76.835 h1.02
  text "VOUT" at 28.956,76.835 h1.02
  text "TPS40210 SEPIC" at 46.736,53.213 h1.02 r90
  text "GND" at 20.066,46.736 h1.02 r90
  text "SW" at 41.275,27.559 h1.02
  text "isns" at 27.305,16.637 h1.02
  text "NwA" at 20.193,6.35 h1.02
  text "GND" at 27.178,4.318 h1.02 r90
  text ".PRJ_Number" at 4.826,1.016 h1.52
  text ".PCB_Rev" at 20.066,1.016 h1.52
  text ".Layer_Name" at 14.656,-21.806 h1.52
Bottom Overlay:
  text ".Layer_Name" at 14.656,-21.806 h1.52
Top Paste:
  text ".Layer_Name" at 14.656,-21.806 h1.52
Bottom Paste:
  text ".Layer_Name" at 14.656,-21.806 h1.52
Top Solder:
  text ".Layer_Name" at 14.656,-21.806 h1.52
  text ".Layer_Name" at 14.656,-21.806 h1.52
Bottom Solder:
  text ".Layer_Name" at 14.656,-21.806 h1.52
Drill Guide:
  text ".Layer_Name" at 14.656,-21.806 h1.52
M1 Board Outline:
  the board outline again, w0.178
  text ".Layer_Name" at 14.656,-21.806 h1.52
M2 Board Dimensions:
  rectangle: 0,-6.985 3.175,-3.81
  rectangle: 3.175,-10.16 12.7,-6.985
  lines w0.178: 0,-6.985 25.4,-6.985 ; 3.175,-10.16 3.175,-3.81 ; 6.35,-10.16 6.35,-3.81 ; 12.7,-10.16 12.7,-3.81 ; 19.05,-10.16 19.05,-3.81 ; 0,-10.16 25.4,-10.16 25.4,-3.81 0,-3.81 0,-10.16
  text ".Layer_Name" at 14.656,-21.806 h1.52
M3 3D STEP Top:
  text ".Layer_Name" at 14.656,-21.806 h1.52
M4 3D STEP Bottom:
  text ".Layer_Name" at 14.656,-21.806 h1.52
M5 Assembly Top:
  lines w0.254: -7.417,-23.626 160.223,-23.626 ; -7.417,-18.462 160.274,-18.462 ; -7.417,-13.297 -7.417,-28.791 94.31,-28.791 160.274,-28.791 160.274,-13.297 -7.404,-13.297 -7.404,-28.791 32.614,-28.791 ; 55.194,-28.791 55.194,-13.297 ; 87.376,-18.462 87.376,-13.297 ; 108.712,-18.462 108.712,-13.297 ; 124.511,-28.956 124.511,-23.804
  text "COMPONENTS MARKED 'DNP' SHOULD NOT BE POPULATED." at 29.299,-8.09 h1.52
  text "ASSEMBLY VARIANT:" at 29.286,-11.024 h1.52
  text ".VariantName" at 55.601,-11.024 h1.52
  text "PCB VIEWED FROM TOP SIDE" at -5.804,-16.654 h1.52
  text "BOARD #:" at 57.099,-16.654 h1.52
  text ".PRJ_Number" at 70.955,-16.654 h1.52
  text "REV:" at 92.405,-16.654 h1.52
  text ".PCB_Rev" at 99.809,-16.654 h1.52
  text "SVN REV:" at 113.69,-16.654 h1.52
  text ".VersionControl_RevNumber" at 126.543,-16.654 h1.52
  text "PLOT NAME =" at -5.804,-27.034 h1.52
  text ".plot_File_Name" at 14.656,-27.034 h1.52
  text "GENERATED    :" at 57.15,-27.034 h1.52
  text ".Print_Date" at 79.235,-27.034 h1.52
  text ".Print_Time" at 97.752,-27.034 h1.52
  text "TEXAS INSTRUMENTS" at 129.87,-27.034 h1.52
M6 Assembly Bottom:
  lines w0.254: -7.429,-18.474 160.261,-18.474 ; -7.379,-23.639 160.261,-23.639 ; 28.334,-28.969 28.334,-23.817 ; 44.133,-18.474 44.133,-13.31 ; 65.468,-18.474 65.468,-13.31 ; 97.65,-28.804 97.65,-13.31 ; 120.231,-28.804 160.249,-28.804 160.249,-13.31 -7.429,-13.31 -7.429,-28.804 58.534,-28.804 160.261,-28.804 160.261,-13.31
  text "COMPONENTS MARKED 'DNP' SHOULD NOT BE POPULATED." at 154.991,-8.077 h1.52
  text ".VariantName" at 128.473,-11.024 h1.52
  text "ASSEMBLY VARIANT:" at 154.864,-11.024 h1.52
  text ".VersionControl_RevNumber" at 26.302,-16.667 h1.52
  text "SVN REV:" at 39.154,-16.667 h1.52
  text ".PCB_Rev" at 53.035,-16.667 h1.52
  text "REV:" at 60.439,-16.667 h1.52
  text ".PRJ_Number" at 81.89,-16.667 h1.52
  text "BOARD #:" at 95.745,-16.667 h1.52
  text "PCB VIEWED FROM BOTTOM SIDE" at 158.648,-16.667 h1.52
  text "TEXAS INSTRUMENTS" at 22.974,-27.047 h1.52
  text ".Print_Time" at 55.093,-27.047 h1.52
  text ".Print_Date" at 73.609,-27.047 h1.52
  text "GENERATED    :" at 95.694,-27.047 h1.52
  text ".plot_File_Name" at 138.189,-27.047 h1.52
  text "PLOT NAME =" at 158.648,-27.047 h1.52
M9 Title Sheet:
  drawing of 57 lines, arcs and shapes, not listed
  text "1" at 18.792,204.127 h1.78
  text "2" at 82.182,204.127 h1.78
  text "3" at 145.411,204.127 h1.78
  text "4" at 209.08,204.127 h1.78
  text "5" at 272.555,204.127 h1.78
  text "6" at 336.182,204.127 h1.78
  text "A" at -10.579,175.095 h1.78
  text "A" at 365.341,175.095 h1.78
  text "B" at -10.579,114.643 h1.78
  text "B" at 365.341,114.643 h1.78
  text "C" at -10.579,54.318 h1.78
  text "C" at 365.341,54.318 h1.78
  text "PROJECT TITLE:" at 288.125,7.048 h1.14
  text ".PRJ_Title" at 289.395,3.662 h1.78
  text "DESIGNED FOR:" at 288.125,-0.597 h1.14
  text ".PRJ_Customer" at 289.395,-4.153 h1.78
  text "D" at -10.579,-5.88 h1.78
  text "D" at 365.341,-5.88 h1.78
  text "FILE NAME:" at 288.125,-8.217 h1.14
  text ".PCB_File_Name_No_Path" at 289.395,-11.265 h1.78
  text "Texas Instruments (TI) and/or its licensors do not warrant the accuracy or completeness of this specification" at 161.9,-15.376 h1.14
  text "ENGINEER:" at 288.125,-15.583 h1.14
  text "LAYOUT BY:" at 326.352,-15.583 h1.14
  text "or any information contained therein. TI and/or its licensors do not warrant that this design will meet" at 160.757,-18.237 h1.14
  text ".PRJ_Engineer" at 289.395,-19.52 h1.78
  text ".PCB_Layout" at 327.635,-19.52 h1.78
  text "the specifications, will be suitable for your application or fit for any particular purpose, or will operate in" at 160.757,-21.099 h1.14
  text ".Layer_Name" at 14.656,-21.806 h1.52
  text "ALTIUM DESIGNER VERSION:" at 326.352,-23.457 h1.14
  text "an implementation. TI and/or its licensors do not warrant that the design is production worthy. You should" at 160.757,-23.961 h1.14
  text "completely validate and test your design implementation to confirm the system functionality for your application." at 161.9,-26.822 h1.14
  text ".print_Scale" at 289.395,-26.843 h1.78
  text ".Application_BuildNumber" at 327.635,-26.843 h1.78
  text "1" at 18.792,-32.093 h1.78
  text "2" at 82.182,-32.093 h1.78
  text "3" at 145.411,-32.093 h1.78
  text "4" at 209.08,-32.093 h1.78
  text "5" at 272.555,-32.093 h1.78
  text "6" at 336.182,-32.093 h1.78
M10 Fab Notes:
  drawing of 185 lines, arcs and shapes, not listed
  text "DESIGN INFORMATION" at 314.478,150.114 h1.52
  text "MIN. TRACK WIDTH:" at 298.106,145.542 h1.52
  text "8" at 325.951,145.542 h1.52
  text "MIL" at 329.881,145.542 h1.52
  text "MIN. CLEARANCE:" at 298.106,142.189 h1.52
  text "0.2" at 324.427,142.189 h1.52
  text "mm" at 329.881,142.189 h1.52
  text "MIN. VIA PAD SIZE:" at 298.106,138.836 h1.52
  text "24" at 325.189,138.836 h1.52
  text "MIL" at 329.881,138.836 h1.52
  text "0.05mm (2MIL)" at 315.759,135.237 h1.52
  text "MINIMUM ANNULAR RING" at 289.744,135.128 h1.52
  text "EXTERNAL" at 333.742,135.128 h1.52
  text "PER" at 294.824,132.131 h1.52
  text "IPC-D-275 CLASS 2 LEVEL C" at 300.412,132.131 h1.52
  text "MIL, HOLES" at 338.213,129.279 h1.52
  text "+/-" at 328.244,129.261 h1.52
  text "+/-" at 349.936,129.261 h1.52
  text "REGISTRATION TOLERANCES:" at 289.744,129.134 h1.52
  text "METAL" at 320.218,129.134 h1.52
  text "5" at 334.853,129.134 h1.52
  text "3" at 356.012,129.134 h1.52
  text "MIL" at 358.964,129.134 h1.52
  text "MATERIAL:" at 287.844,123.813 h1.52
  text "FR-4 High Tg" at 312.9,120.249 h1.52
  text "FR-408" at 298.538,120.031 h1.52
  text "X" at 309.003,120.031 h1.52
  text "OTHER" at 336.333,120.031 h1.52
  text "62 MIL (1.6mm) +/-10%" at 306.668,115.898 h1.52
  text "THICKNESS:" at 289.744,115.789 h1.52
  text "X" at 303.413,115.789 h1.52
  text "OTHER" at 339.305,115.789 h1.52
  text "TOLERANCE:" at 289.744,111.776 h1.52
  text "X" at 311.062,111.776 h1.52
  text "ANSI IPC-6012 TYPE 3 CLASS 2" at 315.81,111.776 h1.52
  text "OTHER +/-" at 315.81,107.814 h1.52
  text "BOW & TWIST:" at 289.744,103.826 h1.52
  text "X" at 311.062,103.826 h1.52
  text "ANSI IPC-6012 TYPE 3 CLASS 2" at 315.81,103.826 h1.52
  text "OTHER +/-" at 315.81,99.8 h1.52
  text "DRILLING:" at 287.844,96.282 h1.52
  text "REFERENCE:" at 289.744,93.31 h1.52
  text "X" at 306.209,93.31 h1.52
  text "AS SHOWN" at 310.958,93.31 h1.52
  text "X" at 329.094,93.31 h1.52
  text "NC_DRILL FILES" at 332.574,93.31 h1.52
  text "PTH MIN COPPER THICKNESS:" at 289.744,89.297 h1.52
  text "X" at 324.039,89.297 h1.52
  text "1MIL" at 327.519,89.297 h1.52
  text "OTHER" at 340.143,89.297 h1.52
  text "BOARD FINISH:" at 287.844,85.259 h1.52
  text "SILKSCREEN:" at 291.787,82.261 h1.52
  text "X" at 315.886,82.261 h1.52
  text "TOP" at 319.086,82.261 h1.52
  text "X" at 328.84,82.261 h1.52
  text "BOTTOM" at 332.066,82.261 h1.52
  text "SILKSCREEN COLOR:" at 291.787,78.02 h1.52
  text "X" at 315.86,78.02 h1.52
  text "WHITE" at 319.086,78.02 h1.52
  text "OTHER" at 332.066,78.02 h1.52
  text "SOLDER RESIST COLOR:" at 291.787,73.702 h1.52
  text "X" at 306.208,69.658 h1.52
  text "GREEN" at 309.434,69.658 h1.52
  text "BLUE" at 324.446,69.658 h1.52
  text "OTHER" at 338.111,69.658 h1.52
  text "IMMERSION GOLD (ENIG)" at 314.794,64.87 h1.52
  text "ENEPIG" at 348.767,64.786 h1.52
  text "SURFACE FINISH:" at 287.844,64.761 h1.52
  text "X" at 310.045,64.761 h1.52
  text "IMM. TIN/SILVER OR EQUIV" at 296.215,60.773 h1.52
  text "OTHER" at 332.574,60.773 h1.52
  text "ARRAY/PANEL:" at 287.844,56.226 h1.52
  text "CUT AND TRIM PER MECH LAYER 1" at 314.794,56.118 h1.52
  text "N.C. ROUTE" at 314.794,52.264 h1.52
  text "X" at 332.04,52.264 h1.52
  text "V. SCORE" at 336.79,52.264 h1.52
  text "CERTIFICATION:" at 287.844,48.784 h1.52
  text "MATERIALS AND WORKMANSHIP FOR ALL PCBS" at 306.259,48.784 h1.52
  text "TO MEET OR EXCEED THE REQUIREMENTS OF:" at 306.259,46.295 h1.52
  text "X" at 296.773,42.828 h1.52
  text "ANSI IPC-A-600F CLASS ->" at 300.303,42.828 h1.52
  text "X" at 341.935,42.828 h1.52
  text "2" at 344.956,42.828 h1.52
  text "1" at 336.955,42.79 h1.52
  text "3" at 353.948,42.79 h1.52
  text "X" at 296.825,38.777 h1.52
  text "UL 94V-0" at 300.303,38.777 h1.52
  text "X" at 317.45,38.777 h1.52
  text "RoHS" at 320.928,38.777 h1.52
  text "OTHER" at 337.296,38.777 h1.52
  text "PER ORDER" at 347.381,38.777 h1.52
  text "ADDITIONAL REQUIREMENTS:" at 287.844,35.195 h1.52
  text "MICROSECTION:" at 289.744,32.274 h1.52
  text "YES" at 312.749,32.274 h1.52
  text "REQUIRED" at 334.631,28.308 h1.52
  text "BARE BOARD ELEC. TEST:" at 289.744,28.236 h1.52
  text "NONE" at 322.909,28.236 h1.52
  text "X" at 331.405,28.236 h1.52
  text "PER ORDER" at 349.668,28.236 h1.52
  text "MANUFACTURER'S UL:" at 289.744,24.248 h1.52
  text "RAIL" at 319.353,24.139 h1.52
  text "METAL" at 331.845,24.139 h1.52
  text "X" at 341.376,24.13 h1.52
  text "SILK" at 344.842,24.139 h1.52
  text ".Layer_Name" at 14.656,-21.806 h1.52
M11 Gerber Information:
  lines w0.254: -7.417,-23.626 160.223,-23.626 ; -7.417,-18.462 160.274,-18.462 ; -7.417,-13.297 -7.417,-28.791 94.31,-28.791 160.274,-28.791 160.274,-13.297 -7.404,-13.297 -7.404,-28.791 32.614,-28.791 ; 55.194,-28.791 55.194,-13.297 ; 87.376,-18.462 87.376,-13.297 ; 108.712,-18.462 108.712,-13.297 ; 124.511,-28.956 124.511,-23.804
  text "ALL ARTWORK VIEWED FROM TOP SIDE" at -5.804,-16.654 h1.52
  text "BOARD #:" at 57.099,-16.654 h1.52
  text ".PRJ_Number" at 70.955,-16.654 h1.52
  text "REV:" at 92.405,-16.654 h1.52
  text ".PCB_Rev" at 99.809,-16.654 h1.52
  text "SVN REV:" at 113.69,-16.654 h1.52
  text ".VersionControl_RevNumber" at 126.543,-16.654 h1.52
  text "LAYER NAME =" at -5.804,-21.806 h1.52
  text "PLOT NAME =" at -5.804,-27.034 h1.52
  text ".plot_File_Name" at 14.656,-27.034 h1.52
  text "GENERATED    :" at 57.15,-27.034 h1.52
  text ".Print_Date" at 79.235,-27.034 h1.52
  text ".Print_Time" at 97.752,-27.034 h1.52
  text "TEXAS INSTRUMENTS" at 129.87,-27.034 h1.52
M12 Stackup:
  drawing of 191 lines, arcs and shapes, not listed
  text "Layer" at 248.681,198.882 h1.52
  text "Name" at 259.092,198.882 h1.52
  text "Material" at 282.708,198.882 h1.52
  text "Thickness" at 304.546,198.882 h1.52
  text "Constant" at 321.052,198.882 h1.52
  text "Board Layer Stack" at 335.526,198.882 h1.52
  text "1" at 248.681,195.834 h1.52
  text "Top Overlay" at 259.092,195.834 h1.52
  text "2" at 248.681,192.786 h1.52
  text "Top Solder" at 259.092,192.786 h1.52
  text "Solder Resist" at 282.708,192.786 h1.52
  text "0.40mil" at 304.546,192.786 h1.52
  text "3.5" at 321.052,192.786 h1.52
  text "3" at 248.681,189.738 h1.52
  text "Top Layer" at 259.092,189.738 h1.52
  text "Copper" at 282.708,189.738 h1.52
  text "1.40mil" at 304.546,189.738 h1.52
  text "4" at 248.681,186.69 h1.52
  text "Dielectric1" at 259.092,186.69 h1.52
  text "FR-4" at 282.708,186.69 h1.52
  text "59.20mil" at 304.546,186.69 h1.52
  text "4.8" at 321.052,186.69 h1.52
  text "5" at 248.681,183.642 h1.52
  text "Bottom Layer" at 259.092,183.642 h1.52
  text "Copper" at 282.708,183.642 h1.52
  text "1.40mil" at 304.546,183.642 h1.52
  text "6" at 248.681,180.594 h1.52
  text "Bottom Solder" at 259.092,180.594 h1.52
  text "Solder Resist" at 282.708,180.594 h1.52
  text "0.40mil" at 304.546,180.594 h1.52
  text "3.5" at 321.052,180.594 h1.52
  text "7" at 248.681,177.546 h1.52
  text "Bottom Overlay" at 259.092,177.546 h1.52
  text ".Layer_Name" at 14.656,-21.806 h1.52
M13 Component Bodies Top:
  text ".Layer_Name" at 14.656,-21.806 h1.52
M14 Component Bodies Bottom:
  text ".Layer_Name" at 14.656,-21.806 h1.52
M15 Courtyards Top:
  text ".Layer_Name" at 14.656,-21.806 h1.52
M16 Courtyards Bottom:
  text ".Layer_Name" at 14.656,-21.806 h1.52
Drill Drawing:
  lines w0.254: 140.917,70.099 141.233,70.099 141.55,69.783 141.866,70.099 142.183,70.099 141.866,70.416 142.183,70.732 141.866,70.732 141.55,71.048 141.233,70.732 140.917,70.732 141.233,70.416 140.917,70.099 ; 140.917,74.846 142.183,74.846 141.55,73.58 140.917,74.846 ; 140.917,77.377 141.55,77.694 142.183,77.377 141.866,78.01 142.183,78.643 141.55,78.327 140.917,78.643 141.233,78.01 140.917,77.377 ; 140.917,81.491 141.233,81.491 141.233,81.175 141.866,81.175 141.866,81.491 142.183,81.491 142.183,82.124 141.866,82.124 141.866,82.44 141.233,82.44 141.233,82.124 140.917,82.124 140.917,81.491
  lines w0.305: 139.192,68.644 193,68.644 ; 139.192,83.833 193,83.833 ; 148.603,64.846 148.603,87.63 ; 157.675,64.846 157.675,87.63 ; 174.476,64.846 174.476,87.63 ; 181.695,64.846 181.695,87.63 ; 139.192,64.846 193,64.846 193,87.63 139.192,87.63 139.192,64.846
  text "Symbol" at 141.47,84.972 h1.83
  text "Quantity" at 149.742,84.972 h1.83
  text "Finished Hole Size" at 158.814,84.972 h1.83
  text "Plated" at 175.616,84.972 h1.83
  text "Hole Type" at 182.834,84.972 h1.83
  text "7" at 149.742,81.175 h1.52
  text "0.300mm (11.81mil)" at 158.814,81.175 h1.52
  text "PTH" at 175.616,81.175 h1.52
  text "Round" at 182.834,81.175 h1.52
  text "42" at 149.742,77.377 h1.52
  text "0.500mm (19.69mil)" at 158.814,77.377 h1.52
  text "PTH" at 175.616,77.377 h1.52
  text "Round" at 182.834,77.377 h1.52
  text "9" at 149.742,73.58 h1.52
  text "1.016mm (40.00mil)" at 158.814,73.58 h1.52
  text "PTH" at 175.616,73.58 h1.52
  text "Round" at 182.834,73.58 h1.52
  text "4" at 149.742,69.783 h1.52
  text "1.270mm (50.00mil)" at 158.814,69.783 h1.52
  text "PTH" at 175.616,69.783 h1.52
  text "Round" at 182.834,69.783 h1.52
  text "62 Total" at 149.742,65.985 h1.52
  text ".Layer_Name" at 14.656,-21.806 h1.52

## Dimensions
0,-10.16 to 25.4,-10.16 on M2 Board Dimensions
0,0 to 49.53,-2.54 on M2 Board Dimensions
0,0 to 0,78.74 on M2 Board Dimensions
